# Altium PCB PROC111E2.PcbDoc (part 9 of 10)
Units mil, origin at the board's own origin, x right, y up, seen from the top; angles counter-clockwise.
Board outline 7700 x 2300 mil, 6 copper layers (Top Layer, GND 1, SIG 1, SIG 2, GND 2, Bottom Layer), stack 78.711 mil thick; 767 components, 596 nets, 2755 pads, 1578 vias.
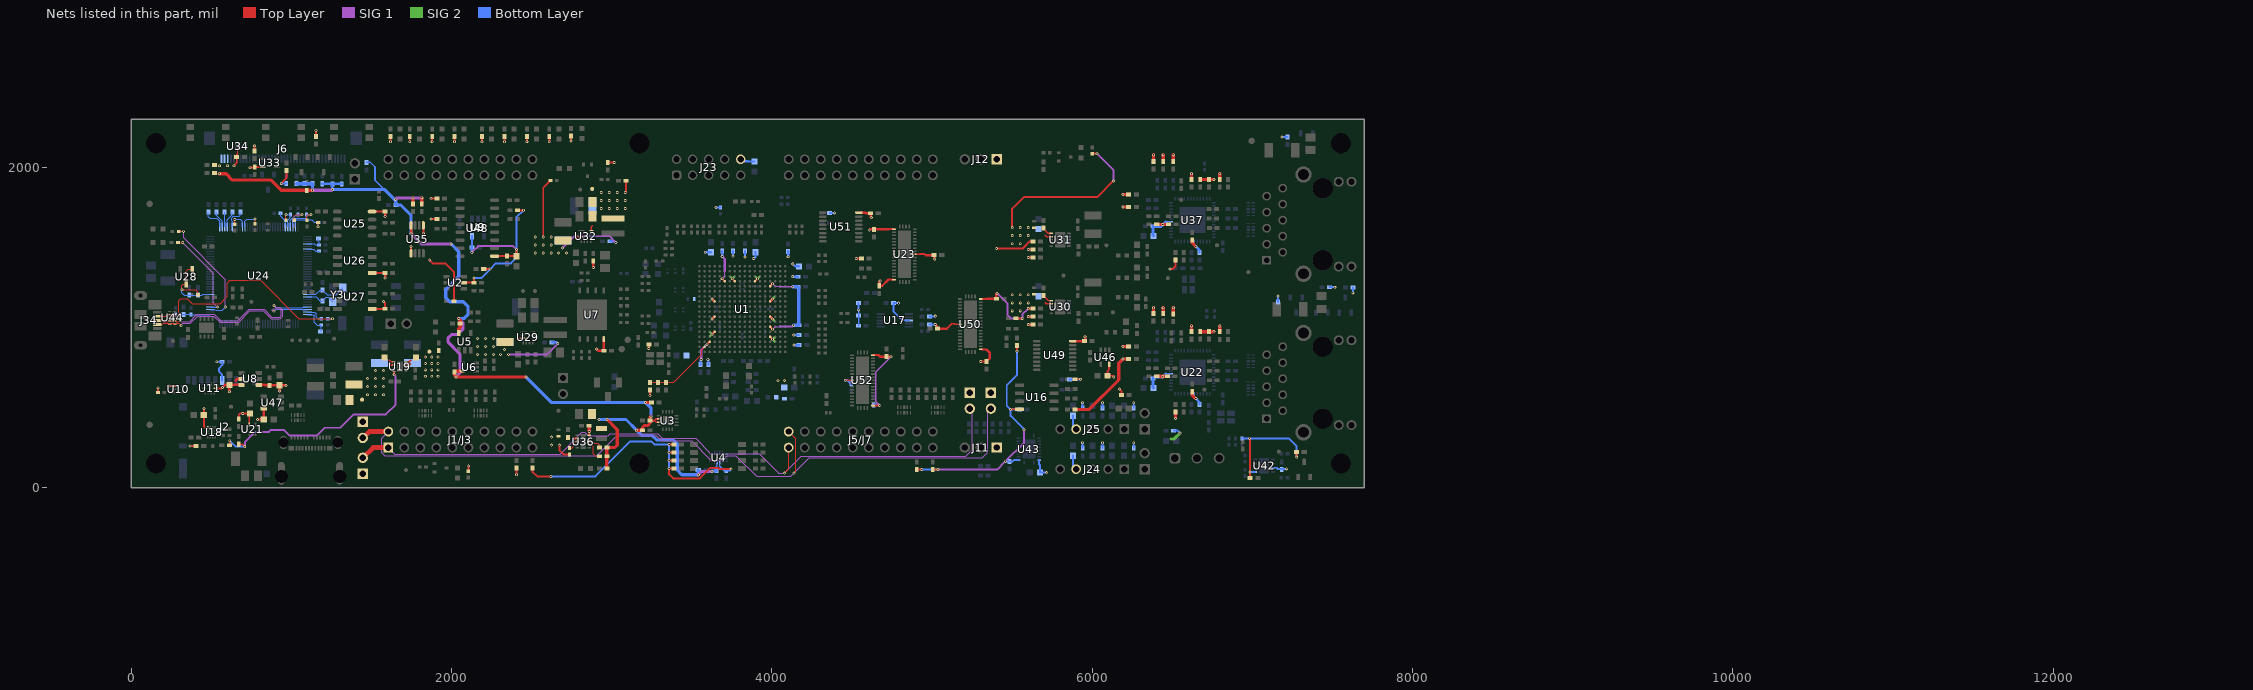
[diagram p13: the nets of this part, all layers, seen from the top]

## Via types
v1: diameter 18, hole 8, Top Layer to Bottom Layer, tented both sides, 1474 vias
v2: diameter 19.68, hole 7.87, Top Layer to Bottom Layer, tented both sides, 104 vias

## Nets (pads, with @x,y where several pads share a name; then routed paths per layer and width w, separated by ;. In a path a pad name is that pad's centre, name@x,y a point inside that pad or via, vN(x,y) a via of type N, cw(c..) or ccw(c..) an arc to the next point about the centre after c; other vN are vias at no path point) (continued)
VDDS_AM263_LDO_1V8: C14.1 C15.1 C16.1 C17.1 C18.1 C98.1 U1.D6 U1.E15 U1.L4 U1.N15 U1.T3 | length 1023.8
  Top Layer w15: v1(3594.38,894.61) U1.T3@3610.12,910.35 ; v1(3625.87,1052.09) U1.L4@3641.62,1067.83 ; v1(3688.87,1304.06) U1.D6@3704.61,1288.31 ; U1.N15@3988.08,1004.84 v1(4003.83,989.09) ; U1.E15@3988.08,1256.81 v1(4003.83,1272.56)
  SIG 1 w4: v1(3688.87,1304.06) 3705,1320.19 3705,1352.62
  SIG 1 w4.75: v1(4003.83,989.09) 4019.95,1005.22 4041.69,1005.22 4042.07,1005.59 4050,1005.59 ; v1(4003.83,1272.56) 4019.57,1256.82 4046.43,1256.82 4049.19,1254.06
  SIG 1 w12: 4049.19,1254.06 v1(4129.81,1254.06) ; 4050,1005.59 4125.13,1005.59 4132.86,1013.32 v1(4134.48,1013.32)
  SIG 1 w15: v1(3557.88,800.12) 3557.88,858.11 v1(3594.38,894.61) ; v1(3688.87,1443.54) 3705,1427.4 3705,1352.62
  Bottom Layer w15: C15.1@3553.63,767.37 3553.63,795.87 v1(3557.88,800.12) ; v1(3688.87,1443.54) C16.1@3688.87,1476.28
  Bottom Layer w20: v1(4129.81,1254.06) C18.1@4162.56,1254.06 4162.92,1254.06 4167.23,1249.74 C17.1@4167.23,1013.32 v1(4134.48,1013.32)
VSD_3V3: C67.1 C71.2 J2.4 U8.5 U8.6 U10.1 U11.10 | length 452.6
  Top Layer w10: v1(235,633.9) U10.1@263.65,633.9
  Top Layer w12: U11.10@523.63,620 561.86,620 566.86,625 v1(568.48,625)
  Top Layer w15: v1(568.48,625) 569.29,625 585.49,641.19 C67.1@611.03,641.19 ; v1(611.13,598.65) 611.03,598.75 C67.1@611.03,641.19 ; 650,667.85 660.75,678.6 U8.5@686.89,678.6 ; U8.6@686.89,641.19 C67.1@611.03,641.19
  Bottom Layer w12: v1(532.67,785.81) 567.73,785.81 568.11,785.43 568.11,766.13 547.13,745.14 547.13,723.87 566.06,704.93 J2.4@566.06,669.61
VSYS_3V3: C4.1 C5.1 C6.1 C7.1 C8.1 C9.1 C10.1 C11.1 C12.1 C13.1 C23.1 C24.1 C43.2 C57.2 C62.2 C66.2 C68.1 C69.1 C70.2 C99.2 C100.2 C111.2 C128.1 C129.1 C130.1 C131.1 C132.1 C133.1 C136.2 C137.2 C138.2 C169.1 C170.1 C171.1 C181.2 C182.2 C205.1 C206.1 C207.1 C208.1 C209.1 C210.1 C213.1 C223.2 C226.2 C236.1 C237.1 C238.2 C239.2 C240.2 C241.2 C242.2 C243.2 C244.2 C245.2 C246.2 C248.1 FB1.1 J9.1 J12.1 J13.1 J23.10 L3.2 R14.1 R15.1 R16.1 R17.1 R31.2 R40.2 R41.2 R55.2 R56.2 R63.2 R64.2 R73.2 R74.2 R108.2 R109.2 R110.2 R111.2 R112.2 R113.2 R114.2 R115.2 R116.2 R147.2 R155.2 R162.2 R175.2 R176.2 R177.2 R178.2 R179.2 R181.2 R203.2 R204.2 R205.2 R206.2 R207.2 R208.2 R209.2 R210.2 R211.2 R224.1 R226.2 R228.2 R230.1 R232.2 R234.2 R244.2 R258.2 R262.2 R263.2 R264.2 R266.2 R267.2 R268.2 R269.1 R270.1 R271.1 R273.2 R277.2 R279.2 R287.1 R288.1 R291.1 R292.1 R295.2 R296.2 R298.1 R305.1 R306.1 R313.2 R314.2 R318.1 R319.1 R320.1 TP9.1 U1.D8 U1.D12 U1.H4 U1.H15 U1.L15 U1.P4 U1.R15 U2.5 U4.2 U7.8 U8.1 U9.5 U16.8 U17.8 U22.18 U22.30 U23.1 U23.17 U23.30 U25.8 U26.1 U27.1 U32.3 U33.5 U34.5 U35.1 U35.5 U37.18 U37.30 U42.5 U43.2 U43.10 U46.5 U48.1 U49.16 U50.1 U50.17 U50.30 U51.16 U52.1 U52.17 U52.30 | length 14115.6
  Top Layer w6: 665,2087.06 U34.5@665,2115.47
  Top Layer w8: v1(640,2010) 657.31,2027.31 C181.2@657.31,2065 657.31,2079.37 665,2087.06
  Top Layer w10: U32.3@2872.01,1603.83 2872.01,1627.63 2878.37,1634 ; v1(5530,851.27) R287.1@5530,887.92
  Top Layer w11: v1(4457.78,670) U52.30@4500.04,670 ; U52.1@4629.96,512.52 v1(4672.27,512.52) ; U52.17@4629.96,827.48 4665.02,827.48 ; 4727.19,1299.02 U23.17@4762.24,1299.02 ; 4727.19,1613.98 U23.1@4762.24,1613.98 ; U23.30@4892.17,1456.5 4922.54,1456.5 4925.72,1459.69 ; 5118.5,1020.04 5121.84,1023.38 5140,1023.38 5143.35,1020.04 U50.30@5173.43,1020.04 ; U50.1@5306.3,862.56 5340,862.56 ; U50.17@5306.3,1177.52 5335,1177.52
  Top Layer w12: v1(165,622.79) 165.31,622.47 R40.2@165.31,594.53 ; v1(740,1997.56) 769.3,1997.56 774.3,2002.56 U33.5@819.08,2002.56 ; R179.2@769.09,2100.98 v1(769.09,2135) ; v1(935,1900) 968.08,1933.08 R178.2@968.08,1980.9 ; R181.2@1151.5,2193.62 v1(1151.5,2230) ; U27.1@1503.27,1115.27 1582.29,1115.27 1582.29,1153.83 v1(1574.25,1161.86) ; v1(1617.87,2160) R279.2@1617.87,2192.56 ; v1(1737.87,2160) R277.2@1737.87,2192.56 ; U35.1@1745.98,1462.4 v1(1745.98,1505.17) ; v1(1822.76,1585.32) U35.5@1822.76,1637.6 ; v1(1860,1421.26) 1881.26,1400 1960.66,1400 2013.62,1347.03 R295.2@2013.62,1163.59 ; v1(1870,1676.88) R270.1@1907.31,1676.88 ; v1(1870,1804.54) R271.1@1907.31,1804.54 ; v1(1877.87,2160) R273.2@1877.87,2192.56 ; v1(2017.87,2160) R267.2@2017.87,2192.56 ; U2.5@2075.37,1279.45 C57.2@2138.78,1279.45 v1(2138.78,1308.13) ; R314.2@2103.52,101.58 v1(2103.52,135) ; v1(2189.29,2160) R266.2@2189.29,2192.56 ; R296.2@2200.03,1365 2239.7,1365 v1(2240,1364.7) ; U48.1@2267.28,1445 C237.1@2345.94,1445 C236.1@2405.95,1445 2404.17,1446.77 v1(2404.17,1486.82) ; v1(2329.29,2160) R264.2@2329.29,2192.56 ; v1(2404.17,80) R55.2@2404.17,122.76 ; R269.1@2411.63,1731.55 v1(2448.33,1731.55) ; v1(2469.29,2160) R263.2@2469.29,2192.56 ; R56.2@2504.17,122.76 2504.17,99.33 2533.82,69.68 v1(2619,69.68) ; v1(2609.29,2160) R262.2@2609.29,2192.56 ; v1(2745.47,2163.94) R313.2@2745.47,2196.5 ; R258.2@2974.53,2029.19 3014.19,2029.19 v1(3015,2030) ; v1(3083.86,1842.84) 3088.62,1847.6 R268.2@3088.62,1915.46 ; v1(3230,867.9) 3230.69,868.59 3230.69,892.84 R31.2@3231.38,893.53 ; v1(3357.56,169.51) R15.1@3388.31,169.51 ; v1(3357.56,219.51) R16.1@3388.31,219.51 ; v1(3357.56,269.51) R17.1@3388.31,269.51 ; R14.1@3388.31,119.51 v1(3357.56,119.51) 3357.56,81.94 3382.37,57.13 3549.61,57.13 3615.35,122.87 3663.22,122.87 3671.1,115 v1(3745,115) ; v1(4526.3,1430.83) 4526.37,1430.9 R288.1@4558.11,1430.9 ; R175.2@4903.31,112.41 v1(4935,112.41) ; 4925.72,1459.69 4925.88,1459.84 4951.65,1459.84 4960,1451.49 ; R176.2@5004.17,112.41 v1(5036.38,112.41) ; 5091.28,992.82 5118.5,1020.04 ; v1(5400.83,1493.61) 5567.49,1493.61 5610.7,1536.82 R155.2@5630.51,1536.82 ; v1(5490,487.03) 5492.11,489.14 U16.8@5545.51,489.14 ; R292.1@5525,1057.02 5562.09,1057.02 v1(5562.51,1056.6) ; R320.1@5892.56,676.73 v1(5927.62,676.73) ; U46.5@6105.59,770.71 6105.59,737.98 6095.59,727.98 C248.1@6095.59,698.38 6126.43,698.38 v1(6134.31,690.5) ; v1@6985,305 v1(6982.5,307.5) 6982.5,305.88 6985,303.38 v1(6985,97.8) 6985,96.18 6986.38,94.8 C226.2@6986.38,60.4 ; v1(7276.76,190) R226.2@7276.76,221.46
  Top Layer w15: U8.1@795.16,641.19 831.92,641.19 835,638.11 862.05,638.11 C69.1@862.1,638.16 C68.1@924.76,638.16 ; v1(924.76,602.5) C68.1@924.76,638.16 ; C68.1@924.76,640.16 C68.1@924.76,638.16 ; v1(965,638.11) 964.95,638.16 C68.1@924.76,638.16 ; U25.8@1502.36,1723.86 C138.2@1584.25,1723.86 v1@1584.25,1692.7 ; U26.1@1503.27,1340 C137.2@1584.25,1340 v1@1584.25,1308.83 ; R162.2@2884,1415.68 2884,1373.93 v1(2884.18,1373.76) ; v1(2904.17,865.58) 2915.61,854.15 C66.2@2950,854.15 U7.8@2950,926.92 ; v1(3625.87,957.6) U1.P4@3641.62,973.35 ; v1(3625.87,1178.07) U1.H4@3641.62,1162.32 ; v1(3751.86,1304.06) U1.D8@3767.61,1288.31 ; U1.D12@3893.59,1288.31 v1(3909.34,1304.06) ; U1.R15@3988.08,941.85 v1(4003.83,926.1) ; U1.L15@3988.08,1067.83 v1(4003.83,1052.09) ; U1.H15@3988.08,1162.32 v1(4003.83,1178.07) ; U51.16@4542.2,1717.48 4585,1717.48 4589.66,1712.82 4616.04,1712.82 C246.2@4616.38,1712.48 4616.38,1689.36 v1(4620.31,1685.42) ; v1(4610,1608.52) 4613.49,1612.01 C241.2@4636.65,1612.01 4638.62,1613.98 4727.19,1613.98 ; 4665.02,827.48 4674.94,817.56 C245.2@4715,817.56 4715.22,817.34 4742.34,817.34 v1(4742.56,817.13) ; v1(4675.31,1290.74) 4670.38,1285.81 C240.2@4670.38,1260.47 4688.64,1260.47 4727.19,1299.02 ; 4960,1451.49 C242.2@5013.22,1451.49 ; C242.2@5012.76,1451.95 C242.2@5013.22,1451.49 ; v1(5016.7,1426.95) 5013.22,1430.43 C242.2@5013.22,1451.49 ; v1(5019.79,1018.97) 5019.79,1018.15 5028.69,1009.26 5028.69,992.82 C111.2@5032.62,992.82 5091.28,992.82 ; v1(5303.59,787.43) 5338.92,787.43 C239.2@5339.88,788.39 5359.07,807.58 5359.07,843.49 5340,862.56 ; 5338.41,1177.52 5339.58,1178.69 C238.2@5401.38,1178.69 5401.38,1208.68 v1(5405.31,1212.62) ; v1(5600,1117.63) R147.2@5630.51,1117.63 ; U49.16@5877.2,914.8 C43.2@5951.38,914.8 5955.31,918.73 v1(5955.31,941.85) ; v1(6485.13,1364.7) 6502.57,1364.7 6520,1382.14 R209.2@6520,1421.38
  Top Layer w20: R318.1@5892.56,488.21 5981.22,488.21 6165,672 6165,776.17 v1(6191.38,802.54) 6191.49,802.65 R108.2@6227.68,802.65 ; v1@6196.38,880.85 v1(6191.38,880.85) 6191.49,880.96 R109.2@6227.76,880.96 ; v1@6196.38,1752.54 v1(6191.38,1752.54) 6191.49,1752.65 R203.2@6227.76,1752.65 ; v1@6196.38,1830.85 v1(6191.38,1830.85) 6191.49,1830.96 R204.2@6227.76,1830.96 ; v1@6382.9,1117.97 v1(6382.9,1122.97) 6383.01,1122.86 R115.2@6383.01,1086.58 ; v1(6382.9,2077.97) 6383.01,2077.86 R210.2@6383.01,2036.59 ; C133.1@6402.76,695.04 6437.44,695.04 v1(6440,692.48) 6442.56,695.04 C132.1@6470.32,695.04 ; C210.1@6402.76,1645.04 6405.32,1642.48 v1(6440,1642.48) 6472.76,1642.48 C209.1@6475.32,1645.04 ; v1@6442.9,1117.97 v1(6442.9,1122.97) 6443.01,1122.86 R116.2@6443.01,1086.59 ; v1(6442.9,2077.97) 6443.01,2077.86 R211.2@6443.01,2036.59 ; v1@6506.17,1118.05 v1(6506.17,1123.05) 6506.28,1122.94 R113.2@6506.28,1086.67 ; v1(6506.17,2078.05) 6506.28,2077.94 R205.2@6506.28,2036.67 ; v1(6520,431.38) 6519.24,431.38 6520,432.14 R114.2@6520,471.38 ; R305.1@6620,973.7 v1(6620,1010) ; R306.1@6620,1923.7 v1(6620,1960) ; C130.1@6625,596.85 6625,577.72 v1(6647.07,555.66) ; C207.1@6625,1546.85 6625,1527.72 v1(6647.07,1505.66) ; R112.2@6674.39,973.7 v1(6760,973.7) ; R207.2@6674.39,1923.7 R208.2@6729.39,1923.7 v1(6760,1923.7) ; R111.2@6796.28,973.31 v1(6796.28,1009.61) ; R206.2@6796.28,1923.31 v1(6796.28,1959.61)
  SIG 1 w10: v1(4672.27,512.52) 4647.86,536.92 4647.86,722.43 v1(4742.56,817.13)
  SIG 1 w12: v1(2125.77,1468.62) 2164.6,1507.46 2383.54,1507.46 v1(2404.17,1486.82) ; v1(5036.38,112.41) 5406.81,112.41 v1(5458.06,163.66) 5574.13,279.73 v1(5574.13,361.28) ; v1(5405.31,1212.62) 5471.05,1146.88 5471.05,1077.3 5491.75,1056.6 v1(5562.51,1056.6) 5563.65,1057.75 5563.65,1081.29 v1(5600,1117.63)
  SIG 2 w15: 3614.77,946.5 v1(3625.87,957.6) 3614.77,968.7 ; 3740.76,1315.16 v1(3751.86,1304.06) 3762.96,1315.16 ; 3898.24,1315.16 v1(3909.34,1304.06) 3920.44,1315.16 ; v1(4003.83,1052.09) 4014.93,1040.98 ; v1(4003.83,1178.07) 4014.93,1189.17 ; 4014.93,915 v1(4003.83,926.1) 4014.93,937.2
  Bottom Layer w7: 3673.95,133.12 U4.2@3673.95,156.28
  Bottom Layer w8: 3673.95,133.12 3701.47,105.6 C62.2@3713.69,105.6 3735.31,105.6 3744.72,115 v1(3745,115)
  Bottom Layer w10: R73.2@4541.17,1010.55 R74.2@4541.17,1074.9 v1(4541.17,1109.9) ; 4814.68,1043.75 U17.8@4855.28,1043.75 ; 6457.72,710.2 U22.30@6491.32,710.2 ; 6457.72,1660.2 U37.30@6491.32,1660.2 ; 6635.02,567.71 U22.18@6635.02,586.18 ; 6635.02,1517.71 U37.18@6635.02,1536.18
  Bottom Layer w12: v1(935,1900) R177.2@966.87,1900 ; v1(2138.78,1308.13) 2183.43,1308.13 v1(2240,1364.7) 2275.3,1400 2370,1400 2404.17,1434.17 v1(2404.17,1486.82) 2404.17,1687.4 v1(2448.33,1731.55) ; v1(2619,69.68) 2896.77,69.68 3115.55,288.47 3246.03,288.47 3264.99,269.51 v1(3357.56,269.51) v1(3357.56,219.51) v1(3357.56,169.51) v1(3357.56,119.51) ; v1(3583.43,1469.95) v1@3583.47,1470 ; v1(3649.94,1749.69) R41.2@3678.01,1749.69 ; R298.1@4362.13,1715.49 v1(4389.19,1715.49) ; v1(4541.17,1109.9) 4541.38,1110.11 R291.1@4541.38,1152.36 ; v1(4790.08,1151.68) 4789.89,1151.87 4758.81,1151.87 C100.2@4758.62,1152.06 4758.62,1099.81 4814.68,1043.75 ; v1(4935,112.41) v1(5036.38,112.41) ; R63.2@4982.83,1019.06 5019.7,1019.06 v1(5019.79,1018.97) ; R64.2@4982.83,1068.43 5017.89,1068.43 v1(5019.79,1070.34) ; v1(5458.06,163.66) C223.2@5483.66,163.66 5501.94,163.66 5510,171.73 U43.2@5538.7,171.73 ; v1(5530,851.27) 5530,702.8 5466.14,638.94 5466.14,510.9 v1(5490,487.03) ; C99.2@5546.38,487.03 v1(5490,487.03) ; U43.10@5574.13,325.27 v1(5574.13,361.28) 5574.13,362.9 5490,447.03 v1(5490,487.03) ; R319.1@5858.93,675 5925.89,675 v1(5927.62,676.73) ; v1(6982.5,307.5) 6935.26,307.5 R244.2@6935,307.24 7227.76,307.24 7276.76,258.25 R228.2@7276.76,221.46 v1(7276.76,190) ; v1(6985,97.8) 6985.27,98.07 U42.5@7017.68,98.07 ; R224.1@7160.2,1158.62 v1(7160.2,1195.94) ; v1(7185,2189.61) 7185.98,2188.62 R230.1@7220,2188.62 ; R232.2@7481.11,1251.28 v1(7515,1251.28) ; v1(7627.57,1216.11) R234.2@7627.57,1250
  Bottom Layer w15: v1(2125.77,1468.62) C70.2@2125.77,1500 2126.56,1500.8 U9.5@2126.56,1570.16 ; v1@3583.47,1470 C6.1@3619.13,1470 ; v1(3599.38,800.12) 3599.38,799.31 3603.63,795.05 C7.1@3603.63,767.37 ; C10.1@3756.08,1476.28 3756.37,1475.99 v1(3756.37,1445.16) ; J23.10@3804.17,2050 3817.5,2036.67 3850,2036.67 3850.17,2036.5 C213.1@3890,2036.5 ; v1(3831.66,1440.59) C11.1@3831.66,1476.28 ; v1(3886.11,1430.04) 3896.79,1440.72 3896.79,1469.78 C5.1@3896.57,1470 ; v1(4100.67,1441.85) C12.1@4100.67,1474.6 ; v1(4129.81,1317.07) C13.1@4162.56,1317.07 ; v1(4129.81,1396.81) 4144.81,1381.81 C4.1@4168.5,1381.81 ; v1(4135.81,952.97) C8.1@4168.56,952.97 ; v1(4137.3,890) C9.1@4170.05,890 ; v1(4457.78,670) 4470.23,670 C243.2@4495.23,645 ; C244.2@4635,516.83 4667.96,516.83 v1(4672.27,512.52) ; v1(6440,692.48) 6457.72,710.2 ; v1(6440,1642.48) 6457.72,1660.2 ; 6635.02,567.71 v1(6647.07,555.66) 6670,532.72 C131.1@6670,518.62 ; 6635.02,1517.71 v1(6647.07,1505.66) 6670,1482.72 C208.1@6670,1468.62
  Bottom Layer w20: C128.1@6382.85,621.24 6379.14,624.96 C129.1@6379.14,681.97 6389.65,692.48 v1(6440,692.48) ; C205.1@6382.85,1571.24 6379.14,1574.96 C206.1@6379.14,1631.97 6429.48,1631.97 v1(6440,1642.48)
  other v1: 4037.34,669.61 4077.34,669.61 1584.23,1308.81 1584.23,1692.68 2933.86,1742.84 2983.86,1742.84 3033.86,1742.84 3083.86,1742.84 2933.86,1792.84 2983.86,1792.84 3033.86,1792.84 3083.86,1792.84 2933.86,1842.84 2983.86,1842.84 3033.86,1842.84
VSYS_3V3_BP: J1/J3.1 J5/J7.41 J9.2 J13.2 | length 4516.2
  Top Layer w5.3: v1(4077.23,90) 4104.17,116.94 J5/J7.41@4104.17,250
  Top Layer w30: J9.2@1445,186.05 1508.95,250 J1/J3.1@1604.17,250
  SIG 1 w4.75: J1/J3.1@1604.17,250 1644.93,209.24 2676.99,209.24 2812.9,345.15 2830.85,345.15 2852.5,323.5 2977.87,323.5 2989,334.63 3286.37,334.63 3314,307 3522.79,307 3618.14,211.65 3919.67,211.65 4041.33,90 v1(4077.23,90) 4182.88,195.65 5210.65,195.65 5251.57,236.57 5251.57,477.5 J13.2@5235.83,493.25
VSYS_5V0: C107.1 C108.1 C161.1 C162.1 C163.1 C167.1 C168.1 C172.1 C173.1 C174.1 C179.1 C180.1 C211.1 C212.1 C224.1 C225.2 J10.1 J11.1 J14.1 J24.4 J25.4 R1.2 R146.2 R149.1 R150.1 R156.2 R157.1 R158.1 R236.2 R237.2 R238.2 R239.2 R240.2 R241.2 R242.2 R243.2 R257.2 R265.2 R302.2 TP8.1 U19.7 U19.8 U29.6 U30.1 U30.2 U31.1 U31.2 U32.6 U42.3 U43.19 | length 3495.9
  Top Layer w10: U19.7@1714.33,765.75 1736.08,765.75 1743.85,773.51 ; U19.8@1714.33,785.43 1734.28,785.43 1743.85,795 ; 2411.63,923.91 2419.56,931.84 U29.6@2448.33,931.84 ; 2773.3,1556.53 2781.23,1564.46 U32.6@2810,1564.46 ; C163.1@5695.21,1198.48 5725.89,1167.8 U30.1@5744.01,1167.8 ; C174.1@5695.21,1617.67 5725.89,1586.99 U31.1@5744.01,1586.99 ; 5705.96,1155 5712.84,1148.12 U30.2@5744.01,1148.12 ; 5705.96,1574.19 5712.84,1567.31 U31.2@5744.01,1567.31
  Top Layer w12: v1(2571.67,1564.46) 2571.67,1872.39 R265.2@2616.4,1917.12 ; v1(3237.35,575.17) 3237.47,575.29 R1.2@3237.47,609.62 ; v1(5500,1623.02) 5500,1741.6 5571.97,1813.56 6031.06,1813.56 v1(6132.5,1915) ; R302.2@6000,2084.58 6000.42,2085 v1(6030,2085) ; v1(6170,615) 6181.38,603.62 R243.2@6181.38,578.2
  Top Layer w15: v1(5600,1017.63) R149.1@5630.51,1017.63 ; v1(5600,1067.63) R150.1@5630.51,1067.63 ; v1(5600,1436.82) R157.1@5630.51,1436.82 ; v1(5600,1486.82) R158.1@5630.51,1486.82
  SIG 1 w12: v1(2355,831.84) 2595.25,831.84 v1(2662.21,898.8) ; v1(2691.67,1495.48) 2765.94,1569.74 2985.26,1569.74 v1(3025,1530) ; v1(6030,2085) 6131.35,1983.65 6131.35,1916.15 v1(6132.5,1915)
  SIG 2 w20: 6492.17,303.97 6512.09,303.97 v1(6548.12,340)
  Bottom Layer w12: U43.19@5668.62,171.73 5668.62,145 5673.54,140.08 C224.1@5673.54,93.47 v1(5715,93.47) ; R238.2@5940,245.75 v1(5940,280) ; R241.2@5940,495.75 v1(5940,530) ; R237.2@6064.18,245.75 v1(6064.18,280) ; R240.2@6064.18,495.75 v1(6064.18,530) ; R236.2@6259.18,245.75 v1(6259.18,280) ; R239.2@6259.18,495.75 v1(6259.18,530) ; R242.2@6508.76,355.53 6532.59,355.53 v1(6548.12,340) ; U42.3@7127.91,123.66 7151.15,123.66 7158.04,116.77 v1(7213.78,116.77)
  Bottom Layer w15: R146.2@2625.95,906.68 2653.52,906.68 2661.4,898.8 v1(2662.21,898.8) ; R156.2@2988.74,1537.88 3016.3,1537.88 3024.19,1530 v1(3025,1530) ; C211.1@5880,198.5 5880,134.18 J24.4@5899.18,115 ; C212.1@5880,448.5 5880,384.18 J25.4@5899.18,365
  other v1: 1835,695 1875,695 1915,695 1835,735 1875,735 1915,735 1835,775 1875,775 1915,775 1835,815 1875,815 1915,815 2160,831.84 2210,831.84 2260,831.84 2305,831.84 2330,862.86 2160,881.84 2210,881.84 2260,881.84 2160,931.84 2210,931.84 2260,931.84 5500,1103.83 5550,1103.83 5500,1153.83 5550,1153.83 5600,1153.83 5500,1203.83 5550,1203.83 5600,1203.83 2521.67,1464.46 2571.67,1464.46 2621.67,1464.46 2666.67,1464.46 2716.67,1464.46 2521.67,1514.46 2571.67,1514.46 2621.67,1514.46 5500,1523.02 5550,1523.02 2521.67,1564.46 2621.67,1564.46 5500,1573.02 5550,1573.02 5600,1573.02 5550,1623.02 5600,1623.02
VSYS_5V0_BP: J1/J3.21 J5/J7.61 J10.2 J14.2 | length 4924.7
  Top Layer w5.3: J5/J7.61@4104.17,350 4149,305.17 4149,101.7 v1(4137.3,90)
  Top Layer w30: J10.2@1445,310 1485,350 J1/J3.21@1604.17,350
  SIG 1 w4.75: J1/J3.21@1604.17,350 1563.41,309.24 1563.41,216.31 1580.54,199.19 2905.37,199.19 3030.06,323.88 3278.62,323.88 3311.34,291.16 3497.34,291.16 3618,170.5 3690.59,170.5 3719.25,199.16 3775.05,199.16 3904.03,70.17 4117.48,70.17 v1(4137.3,90) 4232.3,185 5312.34,185 5347.34,220 5347.34,473.48 J14.2@5367.11,493.25
VSYS_MON_AM263_: C48.1 R1.1 R2.2 U1.U2 | length 450.1
  Top Layer w5.3: R1.1@3237.47,656.87 C48.1@3287.47,656.87 R2.2@3337.66,656.87 3385.72,656.87 3561.66,832.81 3561.66,861.89 U1.U2@3578.63,878.86
VSYS_TA_3V3: C60.2 C61.2 C64.2 C65.2 C183.2 C184.2 C185.1 C186.1 J6.1 J6.2 J6.3 L4.2 R8.1 R10.1 R11.1 R182.1 R183.1 R184.1 R185.1 R186.1 R187.1 R188.1 R189.2 R190.2 R191.2 R192.2 R194.2 R195.2 R315.2 U3.14 U3.15 U4.3 U5.5 U6.5 U35.8 U36.10 | length 7016.6
  Top Layer w10: 3263.33,418.33 3265,420 ; U3.15@3292.94,408.86 3276.14,408.86 3265,420 ; U3.14@3292.94,428.54 3273.54,428.54 3265,420
  Top Layer w12: U36.10@2858.62,327.03 v1(2858.62,350)
  Top Layer w15: v1(1745.98,1585.32) U35.8@1745.98,1637.6 ; C60.2@3238.62,418.33 3263.33,418.33
  Top Layer w20: v1(548.65,1959.61) 591.39,1959.61 630.63,1920.37 871.69,1920.37 935.68,1856.38 R184.1@1094.86,1856.38 1129.33,1856.38 v1(1129.84,1856.89) ; R192.2@1758.28,1771.97 v1(1758.28,1809.27) ; R190.2@1813.28,1771.97 v1(1813.28,1809.27) ; U5.5@2043.91,965.53 2043.91,992.9 2052.85,1001.83 C65.2@2052.85,1024.86 2052.85,1046.62 v1(2043.91,1055.56) ; U6.5@2064.38,726.8 2017.57,726.8 C64.2@2017.57,722.86 2017.65,722.78 2017.65,700.15 v1(2026.56,691.23) v1(2463.34,691.23) ; v1(2858.62,350) C186.1@2858.62,385.96 ; R315.2@2968.62,120 R195.2@2968.62,195.25 R194.2@2968.62,250.25 3019.09,250.25 3033.86,265.02 3033.86,361.14 v1(2970,425) ; v1(3155,358.27) 3155.31,358.58 R10.1@3191.38,358.58 3191.38,375.86 3203.78,388.27 3226.3,388.27 3238.01,399.98 3238.01,417.72 C60.2@3238.62,418.33 3238.62,438.94 v1(3244.69,445) ; v1(3210,530.76) R11.1@3246.38,530.76
  SIG 1 w20: v1(1129.84,1856.89) 1250,1856.89 v1(1255,1861.89) ; v1(1650,1800) 1650.75,1800 1660.03,1809.27 v1(1758.28,1809.27) v1(1813.28,1809.27) ; v1(1745.98,1585.32) 1810.08,1521.22 v1(1995,1521.22) ; v1@2026.95,691.62 2051.87,716.54 2051.87,833.9 1977.14,908.63 1977.14,934.41 1998.96,956.23 2036.23,956.23 2069.25,989.25 2069.25,1030.21 v1(2043.91,1055.56) ; v1(3540,80) 3560,100 v1(3624.83,100)
  Bottom Layer w7: 3653.69,131.2 3658.2,135.71 U4.3@3658.2,156.28
  Bottom Layer w10: R189.2@1468,2030.62 1492.38,2030.62 1521,2002 1521,1920 1579.11,1861.89
  Bottom Layer w12: C61.2@3653.69,105.6 3653.69,131.2
  Bottom Layer w15: R185.1@1190.9,1897.29 1191.81,1896.38 R182.1@1255,1896.38 ; v1(1255,1861.89) R182.1@1255,1896.38 ; R191.2@1312.52,1896.38 R182.1@1255,1896.38
  Bottom Layer w20: R188.1@1029.84,1897.76 R187.1@1079.84,1897.76 R186.1@1129.84,1897.76 v1(1129.84,1856.89) ; v1(1255,1861.89) 1579.11,1861.89 1641,1800 v1(1650,1800) 1651.01,1798.99 R183.1@1651.01,1765 1680,1765 1745.98,1699.02 v1(1745.98,1585.32) ; v1(1995,1521.22) 1996.6,1521.22 2043.91,1473.91 2043.91,1318.66 1962.47,1237.23 1962.47,1185.93 1987.39,1161.01 2071.54,1161.01 2102.25,1130.31 2102.25,1082.94 2074.86,1055.56 v1(2043.91,1055.56) ; v1(2463.34,691.23) 2623.81,530.76 v1(3210,530.76) 3244.69,496.08 v1(3244.69,445) ; v1(2920,425) v1(2970,425) 3088.27,425 v1(3155,358.27) 3188.77,324.5 3253.24,324.5 3280.74,297 3384.5,297 3408,273.5 3408,109.5 3437.5,80 v1(3540,80) 3539.52,80.48 R8.1@3539.52,109.77 ; v1(3624.83,100) 3628.88,104.05 C61.2@3653.69,104.05
  other v1: 548.65,2009.61 598.65,2009.61
VSYS_TA_3V3_EN: R193.1 U36.3 | length 79.7
  Top Layer w5.3: R193.1@2735,246.32 2748.94,246.32 2757.63,255 2757.63,278.54 2766.75,287.66 U36.3@2783.82,287.66
VSYS_TA_3V3_PG: R195.1 U36.7 | length 120.1
  Top Layer w5.3: U36.7@2858.62,267.97 2873.42,267.97 2885,256.39 2885,210 2899.75,195.25 R195.1@2921.38,195.25
VSYS_TA_3V3_SLEEP: R194.1 U36.8 | length 88.5
  Top Layer w5.3: U36.8@2858.62,287.66 2875.14,287.66 2886.41,276.38 2912.81,276.38 2921.38,267.81 R194.1@2921.38,250.25
VUSB_5V0: C101.1 C104.1 C105.1 C106.1 C110.1 C187.1 C188.1 C249.1 L1.2 R91.2 R92.1 R93.1 R94.2 R193.2 TP4.1 U18.12 U19.1 U19.2 U19.4 U21.5 U36.2 U47.5 | length 2138.7
  Top Layer w6: 459.56,374.61 U18.12@476.58,374.61
  Top Layer w10: 1610,773.51 1617.76,765.75 U19.2@1639.52,765.75 ; 1610,795 1619.57,785.43 U19.1@1639.52,785.43 ; U19.4@1639.52,726.38 1639.52,705.69 v1(1640.22,705)
  Top Layer w12: v1(366.44,260.08) R94.2@404.22,260.08 ; v1(452.28,493.25) C101.1@452.28,454.11 452.28,381.89 459.56,374.61 ; R91.2@611.13,263.69 613.55,266.1 v1(613.55,292.1) ; R93.1@669.95,270.68 692.73,270.68 v1(707.73,255.68) ; R92.1@669.95,428.31 670.03,428.39 670.03,455.02 677.06,462.05 v1(695,462.05) C110.1@740,462.05 735.61,457.66 U21.5@735.61,394.13 ; v1(2672.19,265) 2672.19,232.81 2698.05,206.95 R193.2@2735,206.95 ; 2760,307.34 U36.2@2783.82,307.34
  Top Layer w15: v1(787.3,425.41) C249.1@825.37,425.41 U47.5@825.37,493.6
  SIG 1 w12: v1(707.73,255.68) 707.73,283.55 772.01,347.83 857.83,347.83 869,359 953.82,359 987.86,324.96 1157.5,324.96 1205.97,373.43 1303.07,373.43 1386.77,457.13 1589.25,457.13 1650,517.87 1650,695.22 v1(1640.22,705)
  Bottom Layer w12: v1(613.55,292.1) 649.97,255.68 v1(707.73,255.68)
  other v1: 2622.18,265 2622.18,315 1475,580.04 1525,580.04 1575,580.04 1475,630.04 1525,630.04 1575,630.04 1475,680.04 1525,680.04 1575,680.04 1525,730.04 1575,730.04
XDS_DEBUG_ID4: R138.1 R310.1 U24.63 | length 246.2
  Top Layer w5.3: v1(1164.91,1629.18) R310.1@1164.91,1656.39
  Bottom Layer w5.3: U24.63@1023.85,1627.52 1023.85,1664.47 1031.26,1671.88 1124.51,1671.88 1140,1656.39 R138.1@1167.94,1656.39 1167.94,1632.21 v1(1164.91,1629.18)
XDS_DEBUG_ID5: R139.1 R309.1 U24.62 | length 236.8
  Top Layer w5.3: R309.1@1095.89,1669.68 1095.89,1698.95 1101.94,1705 v1(1121.1,1705)
  Bottom Layer w5.3: U24.62@1008.1,1627.52 1008.1,1669.33 1021.25,1682.48 1088.23,1682.48 1093.35,1687.6 R139.1@1093.35,1705 v1(1121.1,1705)
XDS_DEBUG_ID6: R140.1 R308.1 U24.61 | length 207.6
  Top Layer w5.3: R308.1@1016.99,1669.68 1016.99,1697.34 1024.66,1705 v1(1065,1705)
  Bottom Layer w5.3: U24.61@992.35,1627.52 992.35,1668.57 1028.78,1705 R140.1@1039.13,1705 v1(1065,1705)
XDS_DEBUG_ID7: R141.1 R261.1 U24.60 | length 146.1
  Top Layer w5.3: R261.1@965,1669.68 965,1704.32 v1(965.68,1705)
  Bottom Layer w5.3: v1(965.68,1705) R141.1@992.24,1705 992.24,1683.73 976.6,1668.09 U24.60@976.6,1627.52
XDS_EMU0: R311.1 U24.42 | length 117.2
  Top Layer w5.3: R311.1@645,1644.68 v1(645,1674.25)
  Bottom Layer w5.3: v1(645,1674.25) 680.73,1674.25 693.14,1661.84 U24.42@693.14,1627.52
XDS_EMU1: R312.1 U24.43 | length 134.9
  Top Layer w5.3: R312.1@772.07,1647.32 v1(772.07,1676.88)
  Bottom Layer w5.3: U24.43@708.89,1627.52 708.89,1664.61 721.16,1676.88 v1(772.07,1676.88)
XDS_PROGSTAZ1: R259.2 U24.4 | length 566.2
  Top Layer w5.3: R259.2@289.69,1530 v1(320,1530)
  SIG 1 w4.75: v1(320,1530) 510,1340 510,1153.7 v1(536.18,1127.52)
  Bottom Layer w5.3: U24.4@492.35,1127.52 v1(536.18,1127.52)
XDS_PROGSTAZ2: R260.2 U24.3 | length 714.5
  Top Layer w5.3: R260.2@294.69,1600 v1(325,1600)
  SIG 1 w4.75: v1(325,1600) 325,1560 586.18,1298.82 v1(586.18,1127.52)
  Bottom Layer w5.3: U24.3@492.35,1111.77 524.31,1111.77 528.09,1108 566.65,1108 v1(586.18,1127.52)
XDS_VBUS_DETECT: C135.2 R136.1 R137.2 U24.1 | length 267.7
  Bottom Layer w5.3: U24.1@492.35,1080.28 372.88,1080.28 R137.2@371.47,1081.69 C135.2@325.06,1081.69 ; C135.2@325.06,1081.69 R136.1@275.17,1081.69 275.24,1081.76 C135.2@325,1081.76 C135.2@325.06,1081.69
XDSET_1_D_N: J34.2 U24.93 U44.1 U44.10 | length 1217.3
  Top Layer w4.2: J34.2@161.81,1018.49 193.09,1018.49 201.29,1026.68 226.14,1026.68 231.38,1021.44 U44.10@238.56,1021.44 244.8,1021.44 250.05,1026.68 259.01,1026.68 264.25,1021.44 U44.1@271.44,1021.44 278.62,1021.44 283.86,1026.68 296.6,1026.68 v1(310,1013.28)
  SIG 1 w4: v1(310,1013.28) 321.72,1025 366.63,1025 412.89,1071.26 513.89,1071.26 553.2,1031.95 669.21,1031.95 740.01,1102.74 823.7,1102.74 871.44,1055 929.14,1055 945,1070.86 945,1073.42 945,1085.76 945,1108.94 926.42,1127.52 900.13,1127.52 v1(890,1137.65)
  Bottom Layer w4.2: v1(890,1137.65) 903.4,1124.25 1067.83,1124.25 1071.1,1127.52 U24.93@1098.65,1127.52
XDSET_1_D_P: J34.3 U24.94 U44.2 U44.9 | length 1217.1
  Top Layer w4.2: J34.3@161.81,1044.08 192.99,1044.08 201.19,1035.88 226.14,1035.88 231.38,1041.12 U44.9@238.56,1041.12 245.75,1041.12 250.99,1035.88 259.01,1035.88 264.25,1041.12 U44.2@271.44,1041.12 278.62,1041.12 278.62,1040.18 282.92,1035.88 296.6,1035.88 v1(310,1049.28)
  SIG 1 w4: v1(310,1049.28) 310,1040 315,1035 362.49,1035 408.74,1081.26 518.04,1081.26 557.34,1041.95 665.07,1041.95 735.87,1112.74 827.84,1112.74 875.58,1065 925,1065 935,1075 935,1077.56 935,1089.9 935,1104.8 922.28,1117.52 886.99,1117.52 879.55,1110.08 879.55,1105.61 883.52,1101.65 v1(890,1101.65)
  Bottom Layer w4.2: v1(890,1101.65) 903.4,1115.05 1067.83,1115.05 1071.1,1111.77 U24.94@1098.65,1111.77
XDSET_1_ID: J34.4 R130.1 U44.4 U44.7 | length 1435.3
  Top Layer w5.3: J34.4@161.81,1069.67 214.17,1069.67 225,1080.49 U44.7@238.56,1080.49 U44.4@271.44,1080.49 286.73,1080.49 295.48,1089.24 295.48,1166.19 309.08,1179.79 349.55,1179.79 381.06,1148.28 553.25,1148.28 598.65,1193.68 598.65,1277.44 615,1293.79 806.53,1293.79 1046.1,1054.21 v1(1255,1054.21)
  Bottom Layer w5.3: R130.1@1225.19,1054.21 v1(1255,1054.21)
XDSET_1_ID_R: R130.2 U24.95 | length 117.4
  Bottom Layer w5.3: U24.95@1098.65,1096.02 1145.21,1096.02 1155,1086.23 1155,1064.12 1164.91,1054.21 R130.2@1185.82,1054.21
XDSET_NRST: R143.1 U24.70 | length 78.3
  Bottom Layer w5.3: U24.70@1098.65,1489.72 1138.86,1489.72 1151.66,1476.93 R143.1@1171.68,1476.93
XDSET_OSC0: C144.2 U24.88 Y3.1 | length 263.2
  Bottom Layer w5.3: U24.88@1098.65,1206.26 1151.79,1206.26 1178.04,1232.51 C144.2@1192.72,1232.51 1221.4,1203.83 1278.77,1203.83 1318.63,1243.69 Y3.1@1318.63,1247.63
XDSET_OSC1: C143.2 U24.89 Y3.3 | length 187.7
  Bottom Layer w5.3: U24.89@1098.65,1190.51 1152.75,1190.51 1178.31,1164.95 C143.2@1192.72,1164.95 1215.02,1187.24 1229.41,1187.24 Y3.3@1255.64,1161.01
XDSET_RBIAS: R145.2 U24.59 | length 98.3
  Bottom Layer w5.3: R145.2@931.47,1713.62 931.47,1693.52 960.85,1664.13 U24.59@960.85,1627.52
XDSET_TCK: R133.2 U24.35 | length 93.9
  Bottom Layer w5.3: R133.2@580.5,1720.39 582.9,1717.98 U24.35@582.9,1627.52
XDSET_TDI: R135.2 U24.38 | length 139.1
  Bottom Layer w5.3: U24.38@630.15,1627.52 630.15,1661.49 625.48,1666.16 625.48,1682.34 636.91,1693.77 673.66,1693.77 680.5,1700.62 R135.2@680.5,1720.39
XDSET_TMS: R134.2 U24.36 | length 106.1
  Bottom Layer w5.3: U24.36@598.65,1627.52 598.65,1672.74 630.5,1704.59 R134.2@630.5,1720.39
XDSET_UARTA_RX: R129.2 U24.33 | length 147.2
  Bottom Layer w5.3: R129.2@480.5,1720.39 480.5,1691.84 490,1682.34 532.67,1682.34 551.41,1663.6 U24.33@551.41,1627.52
XDSET_UARTA_TX: R131.2 U24.34 | length 108
  Bottom Layer w5.3: R131.2@530.5,1720.39 530.5,1699.5 567.15,1662.85 U24.34@567.15,1627.52
XDSET_VBAT: C142.1 R142.1 U24.68 | length 117.3
  Bottom Layer w5.3: U24.68@1098.65,1521.22 1140,1521.22 1146.29,1514.93 R142.1@1171.68,1514.93 1171.68,1534.93 1167.74,1538.87 C142.1@1167.74,1554.93
XDSET_VREFA: C151.2 C152.2 R144.1 U24.9 U28.1 U28.3 | length 507.4
  Top Layer w5.3: U28.1@378.9,1363.89 353.89,1363.89 341.5,1351.5 U28.3@341.5,1269.4 323.18,1269.4 315,1261.22 v1(315,1235.33) 401.47,1235.33 415,1221.79 R144.1@415,1204.12
  Bottom Layer w5.3: v1(315,1235.33) 315,1216.93 329.89,1202.04 C151.2@360.82,1202.04 C152.2@415.82,1202.04 440.78,1202.04 445,1206.26 U24.9@492.35,1206.26
XDSUSB0VBUS: C134.2 R132.1 U24.96 | length 179.6
  Bottom Layer w5.3: U24.96@1098.65,1080.28 1137.32,1080.28 1142.6,1075 1142.6,1032.15 1160.53,1014.22 R132.1@1185.82,1014.22 C134.2@1185.82,974.22
pads on no net: ?. D15.1S D15.2S D16.1S D16.2S FID1.1 FID2.1 FID3.1 J5.A2 J5.A3 J5.A6 J5.A7 J5.A8 J5.A10 J5.A11 J5.B2 J5.B3 J5.B6 J5.B7 J5.B8 J5.B10 J5.B11 J6.4 J6.5 J6.6 J6.8 J6.9 J6.10 J6.11 J6.12 J6.13 J6.14 J6.15 J6.17 J6.18 J6.19 J6.20 J6.21 J6.22 J6.23 J6.24 J6.29 J6.35 J7. J8. LBL1.0 S2.1 S2.4 SH-J1.0 SH-J2.0 SH-J3.0 SH-J4.0 SH-J5.0 SH-J6.0 SH-J7.0 U1.N3 U3.7 U3.8 U3.9 U3.10 U3.17@3348.05,418.7 U6.1 U8.4 U10.2 U10.5 U11.4 U11.9 U12.3@1835,448.04 U12.8@1835,480.91 U13.3@2180,448.56 U13.8@2180,481.44 U14.3@4825,467.68 U14.8@4825,500.55 U15.3@5035.4,467.82 U15.8@5035.4,500.69 U19.0 U20.1 U20.2 U20.3@1038.54,453.43 U20.8@1038.54,420.56 U20.9 U20.10 U22.14 U22.15 U22.16 U22.17 U22.21 U22.23 U22.24 U24.2 U24.5 U24.6 U24.11 U24.12 U24.13 U24.14 U24.15 U24.18 U24.19 U24.20 U24.21 U24.22 U24.23 U24.24 U24.25 U24.27 U24.29 U24.30 U24.31 U24.32 U24.40 U24.41 U24.44 U24.45 U24.46 U24.49 U24.50 U24.53 U24.54 U24.56 U24.57 U24.65 U24.67 U24.71 U24.72 U24.73 U24.74 U24.75 U24.76 U24.77 U24.78 U24.81 U24.82 U24.83 U24.84 U24.85 U24.86 U24.91 U24.92 U24.102 U24.103 U24.104 U24.105 U24.106 U24.107 U24.108 U24.109 U24.110 U24.111 U24.112 U24.116 U24.117 U24.118 U24.119 U24.120 U24.121 U24.123 U24.124 U24.125 U24.126 U24.127 U24.128 U33.1 U36.4 U36.11@2821.22,262.46 U36.11@2821.22,312.85 U37.14 U37.15 U37.16 U37.17 U37.21 U37.23 U37.24 U38.3@7006.02,788.94 U38.8@6973.14,788.94 U39.3@7005.75,619.6 U39.8@6972.87,619.6 U40.3@7006.02,1738.94 U40.8@6973.14,1738.94 U41.3@7005.75,1609.6 U41.8@6972.87,1609.6 U44.3@271.44,1060.81 U44.5 U44.6 U44.8@238.56,1060.81 U45.7 U45.9@443.89,998.32 U45.9@493.49,998.32 U46.1 U52.15 U52.16
copper on no net: | length 22.3
  Top Layer w10: v1(3594.38,989.09) 3610.12,1004.84

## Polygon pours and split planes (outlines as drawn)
SHIELD3 on Top Layer "Top Layer-SHIELD3" (solid, pour order 100): 7210,2145 7230,2165 7295,2165 7330,2130 7351.52,2130 7470,2130 7470,1908.43 7535,1843.43 7650,1843.43 7650,1429.79 7528.25,1429.79 7505,1406.54 7505,1340 7427.87,1262.87 7265,1262.87 7250,1277.87 7250,1923.31 7210,1963.31
VBUS_TYPEC_5V0 on Top Layer "Top Layer-VBUS_TYPEC_5V0" (solid, pour order 2): 1147.56,332.12 1193.24,332.12 1246.12,385 1265,385 1305,425 1305,658.91 1083.35,658.91 1083.35,578.15 1095.62,565.87 1095.62,494.19 1095.62,456.27 1095.62,384.05
VSYS_5V0 on Top Layer "Top Layer-VSYS_5V0 3" (solid, pour order 50): 2730.81,1453.13 2741.67,1464 2741.2,1480.45 2791.99,1531.23 2791.99,1547.41 2798.1,1553.53 2830.96,1553.53 2830.96,1574.47 2511.67,1574.47 2511.67,1453.13
GND on Top Layer "Top Layer-GND 10" (solid, pour order 233): 3517.52,965.34 3450.35,965.34 3408.32,923.3 3207.35,923.3 3170,885.95 3170,757.86 3249.26,678.6 3391.12,678.6 3586.2,873.68 3586.2,941.78 3559.17,968.81 3520,968.81
GND on Top Layer "Top Layer-GND 9" (solid, pour order 231): 3645.4,951.33 3985,951.33 3985,1290 3660.4,1290 3645.4,1275
VDD_ETH2_1V1_FILT on Top Layer "Top Layer-VDD_ETH2_1V1_FILT" (solid, pour order 257): 6202.73,1475.21 6202.73,1405 6432.19,1405 6432.19,1475.21
VDD_ETH1_1V1_FILT on Top Layer "Top Layer-VDD_ETH1_1V1_FILT" (solid, remove dead copper, pour order 259): 6202.73,1336.32 6202.73,1276.79 6435,1276.79 6435,1336.32
VUSB_5V0 on Top Layer "Top Layer-VUSB_5V0" (solid, pour order 8): 1325,658.91 1325,605 1335,595 1335,475 1595,475 1595,730.83 1622.08,757.91 1650,757.91 1650,833.18 1465,833.18 1465,685 1450,670 1336.09,670
VSYS_3V3 on Top Layer "Top Layer-VSYS_3V3 1" (solid, remove dead copper, pour order 263): 660,2125 660,2103.92 630.73,2074.65 630.73,1999.25 674.75,1999.25 674.75,2125
VDD_ETH2_2V5_FILT on Top Layer "Top Layer-VDD_ETH2_2V5_FILT" (solid, remove dead copper, pour order 255): 6200,1170.6 6208.74,1161.86 6645.76,1161.86 6740.71,1256.82 6740.71,1439.29 6720,1460 6720,1525.03 6729.97,1535 6808,1535 6855,1582 6855,1753 6838,1770 6769.58,1770 6756.49,1756.91 6756.49,1723.86 6770.35,1710 6811.27,1710 6820.42,1700.86 6820.42,1663.05 6797.37,1640 6768.87,1640 6760.4,1631.53 6760.4,1594.19 6751.74,1585.54 6692.5,1585.54 6658.19,1551.23 6658.19,1401.19 6517.47,1260.47 6205.47,1260.47 6200,1255
VDD_ETH1_2V5_FILT on Top Layer "Top Layer-VDD_ETH1_2V5_FILT" (solid, remove dead copper, pour order 253): 6130,988.88 6130,913.65 6135,908.65 6311.35,908.65 6413.38,806.62 6762.73,806.62 6762.73,764.84 6769.66,757.91 6806.29,757.91 6822.8,741.4 6822.8,721.18 6802.77,701.16 6770,701.16 6762.73,693.89 6762.73,653.46 6775,641.19 6830.37,641.19 6855,665.82 6855,795 6774.44,875.56 6468.41,875.56 6363.31,980.67 6258.03,980.67 6245,993.7 6134.82,993.7
GND on Top Layer "Top Layer-GND" (solid, pour order 28): 1660,853.43 1660,696.52 1650,686.52 1650,650 1785,650 1785,701.52 1745.48,701.52 1730,717.01 1730,735 1695,735 1695,853.43 1816.9,853.43 1847.43,883.96 1847.43,956.85 1455,956.85 1455,853.43
VSYS_5V0 on Top Layer "Top Layer-VSYS_5V0" (solid, pour order 24): 1702.92,833.18 1702.92,757.91 1804.17,757.91 1804.17,655.43 1949.39,655.43 1949.39,873.62 1866.75,873.62 1826.3,833.18
GND on Top Layer "Top Layer-GND 2" (solid, pour order 74): 5571.46,1653.41 5571.46,1789.19 6120,1789.19 6120,1671.81 5954.23,1671.81 5929.53,1647.1 5831.61,1647.1 5831.61,1520.09 5864.09,1520.09 5875,1509.19 5875,1475.21 5945,1475.21 5945,1424.19 5765,1424.19 5765,1653.41
VSYS_5V0 on Top Layer "Top Layer-VSYS_5V0 1" (solid, pour order 78): 5749.01,1632.33 5749.01,1559.19 5575,1559.19 5575,1509.19 5490,1509.19 5490,1632.33
VSYS_5V0 on Top Layer "Top Layer-VSYS_5V0 2" (solid, pour order 62): 5749.01,1216.57 5749.01,1140 5575,1140 5575,1090 5490,1090 5490,1216.57
GND on Top Layer "Top Layer-GND 8" (solid, pour order 106): 696.02,230 582.48,230 582.48,36.5 738.53,36.5 738.53,104.22 696.02,146.73
NetR256_2 on Top Layer "Top Layer-NetR256_2" (solid, pour order 176): 4528.38,829.74 4600.43,829.74 4600.43,903.1 4528.38,903.1
SHIELD1 on Top Layer "Top Layer-SHIELD1" (solid, pour order 102): 973.99,352.96 973.99,210 1255,210 1264.76,219.76 1264.76,352.96 1335,352.96 1335,33.93 760,33.93 760,113.93 779.9,133.83 779.9,233.19 881.02,233.19 881.02,352.96
VSYS_TA_3V3 on Top Layer "Top Layer-VSYS_TA_3V3" (solid, pour order 136): 505,2030 611.13,2030 611.13,1940 505,1940
SHIELD4 on Top Layer "Bottom Layer-SHIELD4" (solid, pour order 156): 15,850 190,850 190,1209.07 270,1289.07 270,1333.26 15,1333.26
TPS62913_2_SW on Top Layer "Top Layer-TPS62913_2_SW" (solid, pour order 54): 2891.67,1582.62 2921.91,1552.38 3090,1552.38 3090,1612.62 2916.67,1612.62 2891.67,1587.62
GND on Top Layer "Top Layer-GND 4" (solid, pour order 48): 2827.72,1877.62 2596.67,1877.62 2596.67,1629.58 2757.41,1629.58 2789.37,1597.62 2827.72,1597.62
GND_XDS on Top Layer "Top Layer-GND_XDS" (solid, pour order 124): 341.8,970.68 589.58,970.68 589.58,1035.94 340.03,1035.94 334.13,1030.03 334.13,977 338.86,972.27
SHIELD2 on Top Layer "Top Layer-SHIELD2" (solid, pour order 98): 7370.4,1140 7370.4,1178.69 7285,1178.69 7285,1050 7250,1050 7250,287.87 7265,272.87 7361.33,272.87 7505,416.54 7528.25,439.79 7650,439.79 7650,853.43 7535,853.43 7470,918.43 7470,1140
GND on Top Layer "Top Layer-GND 6" (solid, pour order 138): 489.87,1940 378.92,1940 378.92,2030 490.05,2030 490.05,1940.81
GND on Top Layer "Top Layer-GND 7" (solid, pour order 128): 2827.72,504.82 2605,504.82 2605,345 2747.06,345 2765.04,327.03 2783.82,327.03 2783.82,326.08 2800,309.9 2800,255.68 2767.98,255.68 2767.98,210.09 2872.01,209.89 2872.01,255.68 2840,255.68 2840,339.19 2827.72,351.48
VUSB_5V0 on Top Layer "Top Layer-VSYS_5V0 5" (solid, pour order 126): 2794.34,315 2760,315 2745,330 2605,330 2605,253.69 2698.69,253.69 2725,280 2745,280 2760.83,295.83 2794.83,295.83 2799,300 2799,310.89 2794.34,315.56
VSYS_TA_3V3 on Top Layer "Top Layer-VSYS_TA_3V3 1" (solid, pour order 132): 2852.65,420.34 2842.31,410 2842.31,366.37 2848.5,360.17 2848.5,326.55 2868.35,326.55 2896.71,354.92 2980,354.92 2980,504.25 2852.65,504.25
NetL4_1 on Top Layer "Top Layer-NetL4_1" (solid, pour order 130): 2879.63,324.8 2872.01,317.18 2851.65,317.18 2848.5,314.03 2848.5,303.38 2852.65,299.24 2882,299.24 2895,286.24 2984.39,286.24 2990,291.84 2990,319.8 2985,324.8
VDD_XDS3V3 on Top Layer "Top Layer-VDD_XDS3V3" (solid, pour order 122): 638.15,902.27 638.15,955.61 475.59,955.61 475.59,902.27
VBUS_XDS_5V0 on Top Layer "Top Layer-VBUS_XDS5V0" (solid, pour order 120): 283.58,998.32 208.94,998.32 208.94,884.78 212.21,880.96 420,880.96 420,912.23 462.24,912.27 462.24,956.17 325.73,956.17
VSD_3V3 on Top Layer "Top Layer-VSD_3V3" (solid, pour order 108): 662.48,692.48 630,660 570.07,660 555.83,645.76 555.83,591.18 563.88,583.13 698.13,583.13 715,600 715,683.1 705.62,692.48
VDD_ETH_1V1 on Top Layer "Top Layer-VDD_ETH_1V1" (solid, pour order 76): 6180,1280.86 6135,1280.86 6135,1394.59 6101.86,1427.72 6010,1427.72 6010,1530.63 5996.44,1544.19 5927.62,1544.19 5912.62,1559.19 5849.18,1559.19 5849.18,1631.81 5935,1631.81 5955,1611.81 6180,1611.81
GND on Top Layer "Top Layer-GND 3" (solid, pour order 68): 5548.66,1230 5548.66,1370 6115,1370 6115,1252.62 5954.23,1252.62 5929.53,1227.91 5836.61,1227.91 5836.61,1109.3 5845,1100.91 5864.09,1100.91 5875,1090 5875,1056.02 5945,1056.02 5945,1005 5765,1005 5765,1230
VDD_ETH_2V5 on Top Layer "Top Layer-VDD_ETH_2V5" (solid, pour order 64): 6010,1061.5 6010,977.54 6040.42,947.13 6097.05,947.13 6110,960.08 6110,1007.17 6175,1007.17 6175,1192.62 6175,1206.93 6165,1216.93 6134.31,1216.93 6110,1192.62 5955,1192.62 5935,1212.62 5849.18,1212.62 5849.18,1140 5912.62,1140 5927.62,1125 5996.44,1125 6010,1111.44
VSYS_3V3 on Top Layer "Top Layer-VSYS_3V3" (solid, pour order 52): 2851.04,1877.62 2851.04,1597.62 2880.55,1597.62 2925.55,1642.62 3095,1642.62 3095,1877.62
GND on Top Layer "Top Layer-GND 5" (solid, pour order 40): 2466.04,1245 2235,1245 2235,996.97 2395.73,996.97 2427.7,965 2466.04,965
VSYS_5V0 on Top Layer "Top Layer-VSYS_5V0 4" (solid, pour order 38): 2369.14,820.52 2380,831.38 2379.53,847.83 2430.32,898.61 2430.31,914.8 2436.43,920.91 2469.29,920.91 2469.29,941.85 2150,941.85 2150,820.52
VDD_AM263_1V2 on Top Layer "Top Layer-VDD_AM263_1V2" (solid, pour order 36): 2489.37,1240 2489.37,965 2524.22,965 2569.22,1010 2731.93,1010 2731.93,1240
TPS62913_1_SW on Top Layer "Top Layer-TPS62913_1_SW" (solid, pour order 34): 2530,950 2560.24,919.76 2730,919.76 2730,980 2555,980 2530,955
GND on Top Layer "Top Layer-GND 1" (solid, pour order 18): 1010,820.52 1010,720 1215,720 1215,680.04 1315,680.04 1315,726.51 1445,726.51 1445,820.52
VBUS_TYPEC_5V0 on Bottom Layer "Bottom Layer-VBUS_TYPEC_5V0" (solid, pour order 4): 1019.61,640 1300,640 1300,330 1019.61,330
VUSB_5V0 on Bottom Layer "Bottom Layer-VUSB_5V0" (solid, pour order 20): 1650,560 1664.5,545.5 1664.5,187.5 1687.89,163.66 2332.66,163.66 2356.5,187.5 2530,187.5 2565,222.5 2565,316.5 2596.33,347.83 2707,347.83 2744,310.83 2744,153.5 2616.5,26 1398.5,26 1369,55.5 1369,489 1429.5,549.5 1429.5,806.7 1650,806.7
GND on Bottom Layer "Bottom Layer-GND 2" (solid, pour order 80): 5565,1659.19 5755,1659.19 5755,1799.19 5565,1799.19
SHIELD1 on Bottom Layer "Top Layer-SHIELD1" (solid, pour order 241): 970,333.27 970,173.86 1268.3,173.86 1268.3,333.27 1335,333.27 1335,14.25 760,14.25 760,94.25 779.9,114.15 779.9,213.5 881.02,213.5 881.02,333.27
VDDS_AM263_LDO_1V8 on Bottom Layer "Bottom Layer-VDDS_AM263_LDO_1V8" (solid, pour order 174): 3468.86,751.21 3446.81,773.26 3446.81,888 3497,936.97 3497,1267 3541.78,1311.78 3619.11,1311.78 3650,1342.67 3650,1477.45 3666.16,1493.61 3703.25,1493.61 3719.32,1477.54 3719.32,1426.44 3750.75,1395 4069.75,1395 4069.75,1233.7 3676.49,1233.7 3650,1207.21 3650,915.65 3573,838.65 3573,759.55 3564.67,751.21
VDDA_AM263_3V3 on Bottom Layer "Bottom Layer-VDDA_AM263_3V3" (solid, pour order 140): 4065,1056.95 3693.61,1056.95 3693.61,851.39 3706.98,838.02 3991.66,838.02 3996.98,832.69 3996.98,726.59 3969.92,699.53 3950.47,699.53 3945,705 3945,723.39 3885,723.39 3885,515 3985,515 3985,590 3985,653.01 4065,733.02
GND on Bottom Layer "Bottom Layer-GND 12" (solid, pour order 247): 3387.13,989.09 3368.89,970.85 3216.76,970.85 3193.45,947.54 3193.45,874.17 3248.25,819.37 3358.92,819.37 3375.74,802.54 3417.54,802.54 3427.57,812.57 3427.57,888.68 3468.86,929.96 3468.86,980.8 3460.57,989.09
GND on Bottom Layer "Bottom Layer-GND 7" (solid, pour order 146): 3865,722.41 3865,464.12 3745,464.12 3745,722.41
GND on Bottom Layer "Bottom Layer-GND 11" (solid, pour order 229): 3912.1,1133 3912.1,1100.33 3919.01,1093.42 3919.01,1075.94 3913.4,1070.33 3717.45,1070.33 3704.14,1083.64 3704.14,1112.77 3700.29,1116.63 3700.29,1118.58 3655.73,1118.58 3644.11,1130.2 3644.11,1178.07 3663.36,1197.32 3682.52,1197.32 3704.14,1218.94 3920.87,1218.94 3921.58,1219.61 3972.18,1219.61 3973.5,1220.93 3987.86,1206.57 3987.86,1109.02 3979.17,1100.33 3968.88,1100.33 3936.2,1133
GND on Bottom Layer "Bottom Layer-GND 10" (solid, pour order 251): 3187.54,1455 3167.54,1435 3167.54,1392.46 3185,1375 3319.11,1375 3338.23,1355.88 3531.63,1355.88 3553.51,1377.76 3553.51,1419.82 3518.33,1455
GND on Bottom Layer "Bottom Layer-GND 1" (solid, pour order 94): 3230,1135 3322.46,1135 3338.58,1118.21 3482.32,1118.21 3482.32,1225 3230,1225
VDD_AM263_1V2 on Bottom Layer "Bottom Layer-VDD_AM263_1V2" (solid, pour order 92): 3307.05,1115 3323.86,1098.19 3465.57,1098.19 3465.57,1000.24 3375.88,1000.24 3365.88,990 3230,990 3230,1115
VDD_AM263_1V2 on Bottom Layer "Bottom Layer-VDD_AM263_1V2 1" (solid, pour order 90): 3184.87,1350 3184.87,1240 3465,1240 3465,1350
SHIELD2 on Bottom Layer "Top Layer-SHIELD2" (solid, pour order 192): 7250,329.68 7306.81,272.87 7412.87,272.87 7505,365 7505,416.54 7528.25,439.79 7650,439.79 7650,853.43 7535,853.43 7470,918.43 7470,1140 7250,1140
SHIELD3 on Bottom Layer "Top Layer-SHIELD3" (solid, pour order 190): 7233.03,2130 7210,2106.97 7210,1963.31 7250,1923.31 7250,1277.87 7265,1262.87 7427.87,1262.87 7505,1340 7505,1406.54 7528.25,1429.79 7650,1429.79 7650,1843.43 7535,1843.43 7470,1908.43 7470,2130
GND on Bottom Layer "Bottom Layer-GND 9" (solid, pour order 180): 6545,1468.62 6545,1396.17 6473.24,1396.17 6473.24,1190.62 6710,1190.62 6710,1436.02 6650,1436.02 6650,1508.25 6545,1508.25 6545,1471.48
GND on Bottom Layer "Bottom Layer-GND 6" (solid, pour order 110): 595,40 875.12,40 875.12,190 595,190
VSYS_5V0 on Bottom Layer "Bottom Layer-VSYS_5V0 1" (solid, pour order 82): 5490,1634.19 5490,1508.91 5695,1508.91 5695,1634.19
VDDA_AM263_1V8_LDO on Bottom Layer "Bottom Layer-VDDA_AM263_1V8_LDO" (solid, pour order 144): 3728.62,720 3728.62,460 3635,460 3635,526 3660,551 3660,720
VDD_AM263_1V2 on Bottom Layer "Bottom Layer-VDD_AM263_1V2 3" (solid, pour order 44): 2490,1250 2490,1055 2735,1055 2735,1250
VSYS_3V3 on Bottom Layer "Bottom Layer-VSYS_3V3" (solid, pour order 58): 2851.67,1865 2851.67,1672.62 3116.67,1672.62 3116.67,1865
VUSB_5V0 on Bottom Layer "Bottom Layer-VUSB_5V0 1" (solid, pour order 164): 799,486.02 799,213.5 738.94,213.5 360,213.5 360,440 430,510 505,510 528.98,486.02
GND on Bottom Layer "Bottom Layer-GND 8" (solid, pour order 162): 1000,717.33 1395,717.33 1395,828.31 1000,828.31
VBUS_XDS_5V0 on Bottom Layer "Bottom Layer-VBUS_USBMICRO_5V0" (solid, pour order 152): 275,845.04 195,845.04 195,1015 275,1015
VSYS_3V3 on Bottom Layer "Bottom Layer-VSYS_3V3 1" (solid, pour order 142): 4100,680 4100,530.76 4015,530.76 4015,680
VSYS_TA_3V3 on Bottom Layer "Bottom Layer-VSYS_TA_3V3" (solid, pour order 134): 530,2085 530,1950 609.37,1950 609.37,2085
GND_XDS on Bottom Layer "Bottom Layer-GND_XDS" (solid, pour order 118): 75,1363.74 279.76,1363.74 279.76,1508.25 75,1508.25
SHIELD4 on Bottom Layer "Bottom Layer-SHIELD4" (solid, pour order 116): 15,850 170,850 170,1163.44 275.25,1268.68 275.25,1333.26 15,1333.26
GND on Bottom Layer "Bottom Layer-GND 3" (solid, pour order 72): 5565,1240 5755,1240 5755,1380 5565,1380
VSYS_5V0 on Bottom Layer "Bottom Layer-VSYS_5V0 2" (solid, pour order 70): 5485,1215 5485,1089.72 5695,1089.72 5695,1215
VSYS_5V0 on Bottom Layer "Bottom Layer-VSYS_5V0 3" (solid, pour order 60): 2510,1587.62 2510,1437.62 2766.67,1437.62 2766.67,1572.62 2641.67,1572.62 2626.67,1587.62
GND on Bottom Layer "Bottom Layer-GND 4" (solid, pour order 56): 2596.67,1870 2596.67,1632.62 2791.67,1632.62 2791.67,1870
GND on Bottom Layer "Bottom Layer-GND 5" (solid, pour order 46): 2235,1246.57 2235,1000 2430,1000 2430,1246.57
VSYS_5V0 on Bottom Layer "Bottom Layer-VSYS_5V0 4" (solid, pour order 42): 2149.88,955 2149.88,805 2405,805 2405,940 2280,940 2265,955
GND on Bottom Layer "Bottom Layer-GND" (solid, pour order 32): 1460,960 1460,865 1855,865 1855,960
VSYS_5V0 on Bottom Layer "Bottom Layer-VSYS_5V0" (solid, pour order 30): 1700,805 1700,715 1700,651.28 1945.21,651.28 1945.21,840 1825,840 1825,805
VSYS_3V3 on SIG 2 "SIG 2-VSYS_3V3" (solid, remove dead copper, pour order 196): 2579,177 2644.5,111.5 2644.5,40 460,40 125,375 125,655 195.68,725.68 510,725.68 578.83,793.83 1400.98,793.83 1445,837.85 1445,1825 1423.73,1846.27 1422.45,1845 837.2,1845 800,1882.2 800,1910.57 770.57,1940 389.11,1940 360,1969.11 360,2175 425,2240 7210,2240 7250,2200 7250,2145 7210,2105 7081.9,2105 7063.45,2086.55 7063.45,1271.09 7066.09,1265 7632.05,1265 7665,1232.05 7665,1174.58 7630.42,1140 7156.28,1140 7063.45,1047.17 7063.45,326.97 7024.13,287.65 6569.96,287.65 6212.61,645 5943.01,645 5918.33,669.68 5918.33,1705 5500,1705 5475.79,1680.34 5475.79,1080.37 5545,1015 5545,680 5295,680 5275,660 5275,536.74 5252.93,514.67 4929.5,514.67 4835,609.17 2770.83,609.17 2735,645 2735,925 2775,965 3081.36,965 3496.51,964.7 3533.15,1001.34 3620.8,1001.34 3638.12,984.02 3638.12,951.1 3599.45,912.43 3599.45,844.02 3623.47,820 3990,820 3990,1085.55 3999.45,1095 4055,1095 4055,1165.67 4003.08,1165.67 3995,1173.75 3995,1251.18 3955.82,1290.36 3903.63,1290.36 3891.1,1302.89 3891.1,1310 3879.29,1321.81 3789.22,1321.81 3761.74,1294.32 3626.72,1294.32 3563.83,1357.21 2835,1357.21 2835,1655 2805,1685 1930,1685 1915,1700 1885,1670 1885,990.64 1849.36,955 1770,955 1770,560.76 1375.76,560.76 1350,535 1350,195 1368,177
VDD_XDS3V3 on SIG 2 "SIG 1-VDD_XDS3V3" (solid, pour order 194): 160,840 160,1830 695,1830 695,1745 1355,1745 1355,905 415,905 415,840
VSYS_5V0 on SIG 2 "SIG 1-VSYS_5V0" (solid, remove dead copper, pour order 170): 5885,665 5925,625 6213.46,625 6258.42,580.04 6570.88,267.59 7230,267.55 7230,111.05 7183.95,65 2730.4,65 2569.6,199 1375,199 1375,530 1795,530 1795,919.76 1905,919.76 1905,1660 2821.22,1660 2821.22,1379.42 2494.42,1379.42 2450,1335 2450,722.59 2587.59,585 4815,585 4953.13,445 5268.44,445 5300,476.56 5300,660 5560,660 5560,1020.29 5485,1097.02 5485,1629.65 5515.35,1660 5560,1660 5885,1660
VDD_AM263_1V2 on SIG 2 "SIG 1-VDD_AM263_1V2" (solid, pour order 168): 3470.04,985 3505.4,1020.59 3625.87,1020.59 3647.25,999.21 3647.25,940.31 3615,908.06 3615,844.23 3985,844.23 3985,1070.33 4050,1070.33 4050,1155 3999.19,1155 3990,1164.19 3990,1223.39 3967.26,1246.14 3935.76,1246.14 3866.9,1315 3799.81,1315 3757.37,1272.56 3661.94,1272.56 3599.54,1334.96 2490,1334.96 2490,730.04 2706.09,730.04 2706.09,985 3106.05,985
VDD_ETH2_1V1_FILT on SIG 2 "SIG 2-VDD_ETH2_1V1_FILT" (solid, pour order 12): 6415.73,1433.78 6430.29,1448.34 6430.29,1494.41 6399.19,1525 6399.19,1671.12 6457.21,1671.12 6479.99,1648.34 6823.81,1648.34 6846.59,1671.12 6846.59,1759.22 6825.81,1780 6779.49,1780 6625.24,1934.26 6353.19,1934.26 6259.18,1840.24 6259.18,1473.95 6299.35,1433.78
